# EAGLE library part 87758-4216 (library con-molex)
42 Pin - 2mm Dual Row Single Wafer, Vertical T/H HDR Source: http://www.molex.com/pdm_docs/sd/877580616_sd.pdf
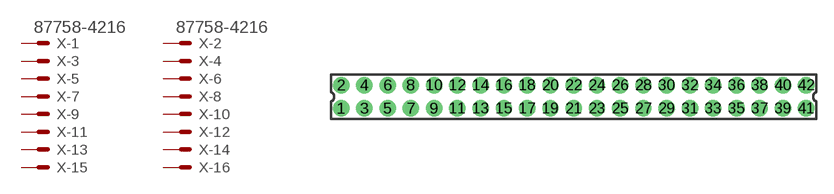
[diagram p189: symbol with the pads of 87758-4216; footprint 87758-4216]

Designator prefix X; gates -1=MV -2=MV -3=M -4=M -5=M -6=M -7=M -8=M -9=M -10=M -11=M -12=M -13=M -14=M -15=M -16=M -17=M -18=M -19=M -20=M -21=M -22=M -23=M -24=M -25=M -26=M -27=M -28=M -29=M -30=M -31=M -32=M -33=M -34=M -35=M -36=M -37=M -38=M -39=M -40=M -41=M -42=M

## 87758-4216 (MPN: 87758-4216; OC_FARNELL: unknown; OC_NEWARK: 25M5693)  [87758-4216]
1  -1:S  pas
2  -2:S  pas
3  -3:S  pas
4  -4:S  pas
5  -5:S  pas
6  -6:S  pas
7  -7:S  pas
8  -8:S  pas
9  -9:S  pas
10  -10:S  pas
11  -11:S  pas
12  -12:S  pas
13  -13:S  pas
14  -14:S  pas
15  -15:S  pas
16  -16:S  pas
17  -17:S  pas
18  -18:S  pas
19  -19:S  pas
20  -20:S  pas
21  -21:S  pas
22  -22:S  pas
23  -23:S  pas
24  -24:S  pas
25  -25:S  pas
26  -26:S  pas
27  -27:S  pas
28  -28:S  pas
29  -29:S  pas
30  -30:S  pas
31  -31:S  pas
32  -32:S  pas
33  -33:S  pas
34  -34:S  pas
35  -35:S  pas
36  -36:S  pas
37  -37:S  pas
38  -38:S  pas
39  -39:S  pas
40  -40:S  pas
41  -41:S  pas
42  -42:S  pas

## Footprint 87758-4216 (pad centres in mm)
42 Pin - 2mm Dual Row Single Wafer, Vertical T/H HDR Source: http://www.molex.com/pdm_docs/sd/877580616_sd.pdf
drill 0.9 pad 1.27 round: 1 -20,-1; 2 -20,1; 3 -18,-1; 4 -18,1; 5 -16,-1; 6 -16,1; 7 -14,-1; 8 -14,1; 9 -12,-1; 10 -12,1; 11 -10,-1; 12 -10,1; 13 -8,-1; 14 -8,1; 15 -6,-1; 16 -6,1; 17 -4,-1; 18 -4,1; 19 -2,-1; 20 -2,1; 21 0,-1; 22 0,1; 23 2,-1; 24 2,1; 25 4,-1; 26 4,1; 27 6,-1; 28 6,1; 29 8,-1; 30 8,1; 31 10,-1; 32 10,1; 33 12,-1; 34 12,1; 35 14,-1; 36 14,1; 37 16,-1; 38 16,1; 39 18,-1; 40 18,1; 41 20,-1; 42 20,1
